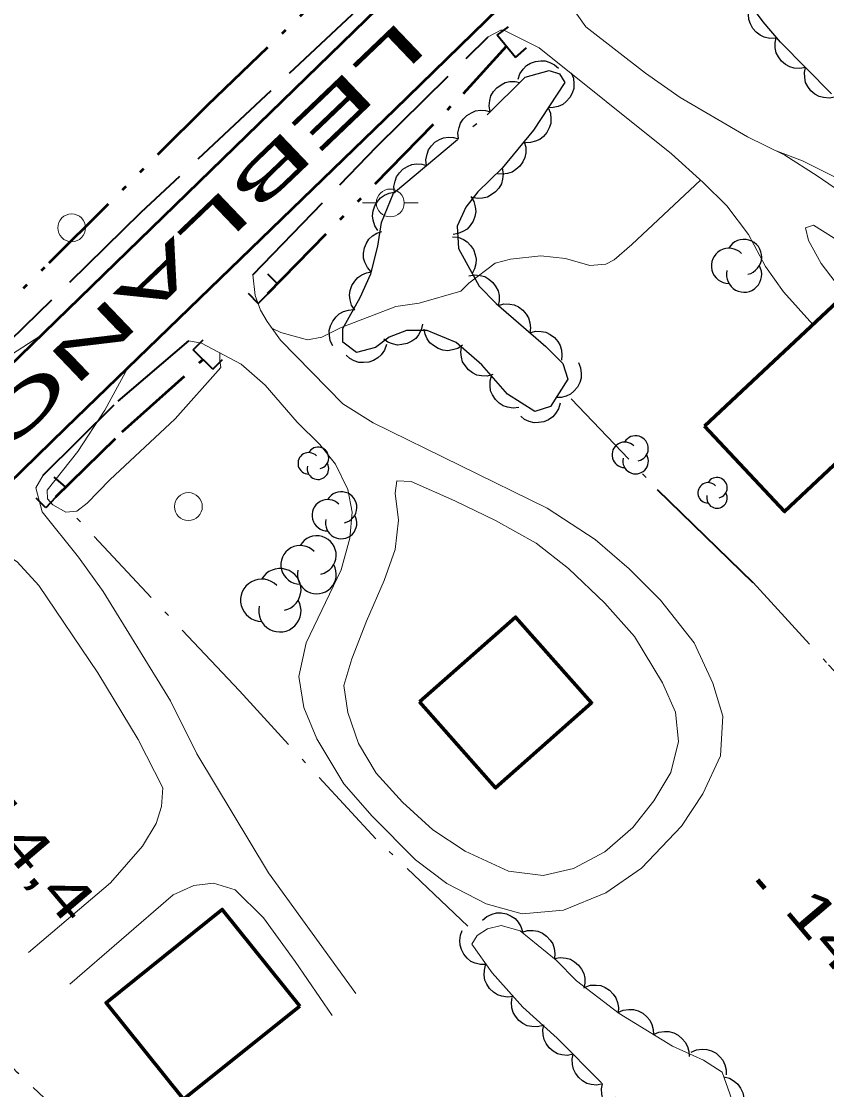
# Model space of a CAD drawing. Extents: x 386081 to 389416, y 5130568 to 5134082.
# Drawn here: x 387358.2 to 387416.1, y 5132218.5 to 5132295.3 of the extents above; entities that cross this region are included whole.
import ezdxf

# ---------------------------------------------------------------- set-up
doc = ezdxf.new("R2010")
doc.units = 0
doc.header["$LTSCALE"] = 1.2
for name, pattern in [('DASH_DOUBLE_DOT', [9.2, 5, -1.2, 0.3, -1.2, 0.3, -1.2]), ('DOT_DASHED', [7.7, 5, -1.2, 0.3, -1.2]), ('LONG_DASHED', [7.5, 6, -1.5])]:
    doc.linetypes.add(name, pattern=pattern)
for name, color, linetype, lineweight in [('19', 7, 'Continuous', 13), ('2', 7, 'Continuous', 13), ('21', 7, 'LONG_DASHED', 35), ('26', 7, 'Continuous', 35), ('3', 7, 'Continuous', 140), ('31', 7, 'Continuous', 70), ('36', 7, 'Continuous', 13), ('37', 7, 'Continuous', 13), ('4', 7, 'DASH_DOUBLE_DOT', 53), ('41', 7, 'DOT_DASHED', 25), ('44', 7, 'Continuous', 25)]:
    doc.layers.add(name, color=color, linetype=linetype, lineweight=lineweight)

msp = doc.modelspace()

# ---------------------------------------------------------------- linework, layer by layer
at = {"layer": '19'}
for points in [[(387422.4, 5132279.4), (387415.39, 5132284.23), (387413.06, 5132285.71), (387410.38, 5132287.04), (387405.54, 5132289.86), (387403.04, 5132291.62), (387398.75, 5132294.94), (387397.82, 5132296.26), (387397.26, 5132297.49), (387397.04, 5132298.28), (387397.11, 5132299.05)], [(387391.74, 5132294.23), (387392.64, 5132294.7), (387392.87, 5132294.71), (387395.39, 5132293.43), (387404.91, 5132285.8), (387407.18, 5132283.76), (387408.88, 5132282.08), (387410.44, 5132280.01), (387411.67, 5132277.71), (387412.95, 5132275.88), (387415.07, 5132273.55)], [(387417.37, 5132275.7), (387415.66, 5132277.92), (387414.75, 5132279.57), (387414.55, 5132280.48), (387415.11, 5132280.68), (387420.6, 5132277.22)], [(387370.22, 5132272.37), (387371.13, 5132272.19), (387373.99, 5132270.69), (387375.7, 5132269.18), (387378.01, 5132266.51), (387379.63, 5132264.92), (387380.77, 5132263.49), (387381.65, 5132261.67), (387381.95, 5132260.05), (387381.78, 5132258.18), (387381.18, 5132255.9), (387378.66, 5132250.65), (387378.13, 5132248.24), (387378.48, 5132246.01), (387379.41, 5132243.75), (387381.36, 5132240.51), (387383.4, 5132238.18), (387386.5, 5132235.04), (387388.76, 5132233.34), (387391.6, 5132231.88), (387394.18, 5132231.17), (387397.16, 5132231.44), (387400.2, 5132232.68), (387402.76, 5132234.45), (387405.63, 5132237.48), (387407.16, 5132239.79), (387408.44, 5132242.53), (387408.61, 5132245.37), (387407.88, 5132247.75), (387406.53, 5132250.65), (387404.11, 5132253.72), (387401.86, 5132255.97), (387399.42, 5132258.09), (387395.97, 5132260.34), (387383.46, 5132266.48), (387381.28, 5132267.83), (387376.8, 5132272.42), (387375.86, 5132273.76), (387375.38, 5132274.58), (387374.98, 5132275.62), (387374.83, 5132277.12)], [(387382.22, 5132225.44), (387375.94, 5132234.12), (387370.79, 5132242.67), (387368.9, 5132246.48), (387364.06, 5132254.34), (387362.3, 5132256.8), (387359.68, 5132260.08), (387359.22, 5132261.8), (387359.74, 5132262.7)], [(387354.62, 5132257.4), (387355.58, 5132257.49), (387356.56, 5132257.32), (387357.89, 5132256.48), (387359.45, 5132254.78), (387363.68, 5132248.49), (387366.57, 5132243.7), (387368.35, 5132240.22), (387368.26, 5132238.88), (387367.87, 5132237.67), (387366.88, 5132236.04), (387364.58, 5132233.4), (387358.69, 5132228.38)], [(387361.67, 5132226.11), (387369.09, 5132232.53), (387370.59, 5132233.2), (387371.99, 5132233.37), (387373.55, 5132232.9), (387375.59, 5132230.87), (387377.86, 5132227.74), (387380.53, 5132223.86)]]:
    msp.add_lwpolyline(points, dxfattribs=at)
msp.add_lwpolyline([(387386.2, 5132262.26), (387389.34, 5132260.86), (387392.26, 5132259.44), (387395.18, 5132257.83), (387397.5, 5132256), (387400.13, 5132253.51), (387402.26, 5132251.12), (387404.27, 5132247.78), (387405.2, 5132245.66), (387405.41, 5132243.57), (387404.87, 5132241.34), (387403.64, 5132239.3), (387402.13, 5132237.38), (387400.11, 5132235.63), (387397.87, 5132234.44), (387395.68, 5132233.93), (387393.2, 5132234.24), (387390.08, 5132235.67), (387387.75, 5132237.22), (387385.58, 5132239.2), (387383.69, 5132241.29), (387382.41, 5132243.41), (387381.65, 5132245.65), (387381.36, 5132247.59), (387381.94, 5132249.51), (387382.99, 5132252.2), (387384.25, 5132255.13), (387385.04, 5132257.36), (387385.28, 5132259.47), (387385.04, 5132261.42), (387385.18, 5132262.29)], close=True, dxfattribs=at)
at = {"layer": '2'}
for points in [[(387412.43, 5132286.03), (387414.32, 5132285.3), (387417.34, 5132283.8), (387424.57, 5132280.68), (387425.03, 5132281.2), (387427.59, 5132283.53), (387429.06, 5132284.43), (387430.72, 5132285.09), (387432.64, 5132285.42), (387435.02, 5132285.48), (387435.31, 5132285.52)], [(387376.19, 5132273.28), (387376.83, 5132272.97), (387378.76, 5132272.43), (387379.77, 5132272.63), (387381.17, 5132273.33), (387385.09, 5132274.84), (387386.77, 5132275.07), (387389.78, 5132275.94), (387390.34, 5132276.5), (387392.24, 5132277.95), (387393.35, 5132278.24), (387395.52, 5132278.48), (387397.3, 5132278.28), (387399.05, 5132277.78), (387400.2, 5132277.87), (387400.78, 5132278.18), (387402.07, 5132279.28), (387407, 5132283.92)], [(387292.79, 5132207.75), (387292.79, 5132208.61), (387293.85, 5132210.26), (387295.35, 5132212.1), (387296.15, 5132212.9), (387299.2, 5132216.39), (387299.95, 5132217.37), (387301.13, 5132219.15), (387304.17, 5132222.13), (387330.72, 5132247.76), (387336.49, 5132252.9), (387339.94, 5132256.42), (387350.61, 5132266.83), (387352.3, 5132268.05), (387359.5, 5132272.69)], [(387365.84, 5132270.42), (387364.19, 5132267.38), (387362.24, 5132264.41), (387360.03, 5132261.63), (387360.06, 5132261), (387360.45, 5132260.57), (387361.39, 5132260.04), (387362.18, 5132260.13), (387362.91, 5132260.69), (387364.54, 5132262.36), (387369.23, 5132266.75), (387372.52, 5132270.44), (387372.44, 5132270.96), (387372.46, 5132271.49)]]:
    msp.add_lwpolyline(points, dxfattribs=at)
at = {"layer": '21'}
for points in [[(387559.78, 5132467.9), (387547.05, 5132455.63), (387529.68, 5132439.13), (387509.18, 5132419.17), (387475.58, 5132387.34), (387460.99, 5132373.08), (387444.91, 5132357.61), (387431.84, 5132344.48), (387417.82, 5132331.23), (387408.06, 5132321.28), (387397.84, 5132311.09), (387382.67, 5132296.51), (387366.78, 5132281.59), (387351.61, 5132266.75), (387342.14, 5132257.75), (387333.42, 5132249.15), (387330.68, 5132246.34), (387329.25, 5132245.05), (387325.03, 5132240.88), (387315.96, 5132231.51), (387312.59, 5132228.76), (387303.02, 5132219.72), (387274.55, 5132192.18)], [(387374.83, 5132277.12), (387383.74, 5132286.34), (387391.74, 5132294.23)], [(387359.74, 5132262.7), (387365.13, 5132268.03), (387370.22, 5132272.37)]]:
    msp.add_lwpolyline(points, dxfattribs=at)
at = {"layer": '21', "linetype": 'Continuous', "lineweight": 53}
for points in [[(387012.51, 5131910.8), (387021.08, 5131926.01), (387027.11, 5131935.62), (387032.84, 5131944.26), (387041.79, 5131956.43), (387052.62, 5131969.96), (387063.03, 5131981.26), (387078.48, 5131997.51), (387098.33, 5132017.4), (387121.9, 5132040.2), (387177.29, 5132094.24), (387231.65, 5132148.34), (387255.86, 5132172.16), (387275.84, 5132191.54), (387323.76, 5132237.29), (387346.1, 5132259.65), (387398.36, 5132310.48), (387454.62, 5132364.63)], [(387190.72, 5132099), (387248.29, 5132155.99), (387268.9, 5132176.09), (387312.71, 5132218.45), (387334.53, 5132239.9), (387361.38, 5132266.11), (387385.04, 5132289.01), (387424.23, 5132327.22)]]:
    msp.add_lwpolyline(points, dxfattribs=at)
at = {"layer": '26'}
for p, q in [((387392.39, 5132294.33), (387393.19, 5132294.93)), ((387393.69, 5132292.73), (387392.39, 5132294.33)), ((387393.69, 5132292.73), (387394.49, 5132293.43)), ((387376.6, 5132276.46), (387375.9, 5132277.16)), ((387376.6, 5132276.46), (387375.9, 5132277.16)), ((387375.2, 5132275.06), (387374.5, 5132275.76)), ((387375.2, 5132275.06), (387374.5, 5132275.76)), ((387376.6, 5132276.46), (387375.2, 5132275.06)), ((387376.6, 5132276.46), (387375.2, 5132275.06)), ((387370.54, 5132271.73), (387371.24, 5132272.43)), ((387370.54, 5132271.73), (387371.24, 5132272.43)), ((387371.94, 5132270.33), (387370.54, 5132271.73)), ((387371.94, 5132270.33), (387370.54, 5132271.73)), ((387371.94, 5132270.33), (387372.64, 5132271.03)), ((387371.94, 5132270.33), (387372.64, 5132271.03)), ((387361.35, 5132261.86), (387360.55, 5132262.56)), ((387361.35, 5132261.86), (387360.55, 5132262.56)), ((387361.35, 5132261.86), (387359.95, 5132260.36)), ((387361.35, 5132261.86), (387359.95, 5132260.36)), ((387359.95, 5132260.36), (387359.25, 5132261.06)), ((387359.95, 5132260.36), (387359.25, 5132261.06))]:
    msp.add_line(p, q, dxfattribs=at)
at = {"layer": '3'}
msp.add_line((387411.1, 5132233.62), (387411.61, 5132233.01), dxfattribs=at)
at = {"layer": '31'}
for points in [[(387407.29, 5132266.22), (387418.37, 5132276.62), (387424.55, 5132270.04), (387419.78, 5132265.55), (387419.34, 5132266.01), (387413.04, 5132260.09)], [(387386.8, 5132246.4), (387393.7, 5132252.51), (387399.17, 5132246.34), (387392.27, 5132240.22)], [(387378.19, 5132224.54), (387369.84, 5132217.84), (387364.27, 5132224.78), (387372.62, 5132231.49)]]:
    msp.add_lwpolyline(points, close=True, dxfattribs=at)
at = {"layer": '36'}
for p, q in [((387382.7, 5132282.28), (387383.7, 5132282.28)), ((387386.7, 5132282.28), (387385.7, 5132282.28))]:
    msp.add_line(p, q, dxfattribs=at)
for centre in [(387384.694, 5132282.28), (387361.798, 5132280.49), (387370.188, 5132260.45)]:
    msp.add_circle(centre, 1, dxfattribs=at)
at = {"layer": '37', "lineweight": 25}
for p, q in [((387403.88, 5132261.65), (387410.76, 5132254.97)), ((387403.91, 5132261.68), (387410.79, 5132255))]:
    msp.add_line(p, q, dxfattribs=at)
at = {"layer": '4'}
for points in [[(387309.12, 5132228.67), (387320.14, 5132238.92), (387332.54, 5132251.32), (387345.1, 5132263.26), (387360.19, 5132277.97), (387371.56, 5132289.32), (387382.38, 5132299.68), (387391.28, 5132308.57), (387395.06, 5132312.61), (387395.98, 5132313.9), (387396.57, 5132318.63), (387396.55, 5132322.58), (387396.22, 5132327.79)], [(387375.9, 5132275.76), (387389.95, 5132290.15), (387393.05, 5132293.54)], [(387360.65, 5132261.16), (387365.44, 5132265.82), (387371.24, 5132271.03)]]:
    msp.add_lwpolyline(points, dxfattribs=at)
at = {"layer": '41'}
msp.add_line((387397.71, 5132268.2), (387403.91, 5132261.68), dxfattribs=at)
for points in [[(387390.27, 5132230.29), (387383.66, 5132236.56), (387373.85, 5132247.19), (387362.06, 5132259.73)], [(387410.79, 5132255), (387416.19, 5132249.07), (387424.53, 5132240.16)], [(387363.42, 5132214.58), (387357.88, 5132219.77), (387345.26, 5132233.24), (387341.64, 5132237.16)]]:
    msp.add_lwpolyline(points, dxfattribs=at)
at = {"layer": '44', "linetype": 'DOT_DASHED'}
msp.add_lwpolyline([(387416.42, 5132290.12), (387412.74, 5132293.83), (387411.51, 5132295.31), (387410.04, 5132297.29), (387409.56, 5132298.77), (387410.06, 5132299.75), (387410.81, 5132300.24), (387412.29, 5132299.74), (387415.61, 5132297.14), (387419.79, 5132294.42)], dxfattribs=at)
at = {"layer": '44'}
for points in [[(387412.39, 5132294.12), (387411.98, 5132294.1), (387411.58, 5132294.2), (387411.28, 5132294.33), (387411, 5132294.55), (387410.76, 5132294.82), (387410.58, 5132295.16), (387410.47, 5132295.47), (387410.45, 5132295.82), (387410.49, 5132296.19), (387410.61, 5132296.53)], [(387414.54, 5132292.01), (387414.13, 5132291.94), (387413.73, 5132291.98), (387413.41, 5132292.06), (387413.1, 5132292.24), (387412.82, 5132292.48), (387412.6, 5132292.79), (387412.44, 5132293.07), (387412.37, 5132293.42), (387412.36, 5132293.79), (387412.43, 5132294.14)], [(387393.88, 5132291.18), (387394.02, 5132291.57), (387394.25, 5132291.9), (387394.48, 5132292.15), (387394.78, 5132292.32), (387395.13, 5132292.45), (387395.51, 5132292.49), (387395.84, 5132292.49), (387396.17, 5132292.38), (387396.5, 5132292.21), (387396.78, 5132291.98)], [(387416.65, 5132289.88), (387416.24, 5132289.81), (387415.84, 5132289.85), (387415.52, 5132289.93), (387415.22, 5132290.11), (387414.93, 5132290.35), (387414.71, 5132290.66), (387414.55, 5132290.94), (387414.49, 5132291.29), (387414.47, 5132291.66), (387414.54, 5132292.01)], [(387397.69, 5132291.63), (387397.86, 5132291.25), (387397.9, 5132290.84), (387397.89, 5132290.51), (387397.78, 5132290.18), (387397.6, 5132289.86), (387397.34, 5132289.57), (387397.1, 5132289.36), (387396.77, 5132289.22), (387396.41, 5132289.13), (387396.05, 5132289.12)], [(387391.88, 5132288.84), (387391.81, 5132289.25), (387391.85, 5132289.65), (387391.93, 5132289.97), (387392.11, 5132290.28), (387392.35, 5132290.56), (387392.66, 5132290.78), (387392.95, 5132290.94), (387393.3, 5132291), (387393.67, 5132291.02), (387394.02, 5132290.94)], [(387389.6, 5132286.89), (387389.56, 5132287.31), (387389.64, 5132287.71), (387389.74, 5132288.02), (387389.94, 5132288.31), (387390.2, 5132288.57), (387390.54, 5132288.76), (387390.83, 5132288.9), (387391.18, 5132288.94), (387391.55, 5132288.92), (387391.9, 5132288.82)], [(387396.05, 5132289.12), (387396.21, 5132288.74), (387396.25, 5132288.33), (387396.24, 5132288), (387396.13, 5132287.67), (387395.96, 5132287.34), (387395.7, 5132287.06), (387395.45, 5132286.85), (387395.13, 5132286.71), (387394.77, 5132286.62), (387394.41, 5132286.61)], [(387387.3, 5132284.96), (387387.26, 5132285.38), (387387.34, 5132285.78), (387387.44, 5132286.09), (387387.65, 5132286.38), (387387.91, 5132286.64), (387388.24, 5132286.83), (387388.53, 5132286.97), (387388.88, 5132287.01), (387389.25, 5132286.99), (387389.6, 5132286.89)], [(387394.31, 5132286.68), (387394.43, 5132286.28), (387394.43, 5132285.88), (387394.38, 5132285.55), (387394.23, 5132285.23), (387394.02, 5132284.93), (387393.73, 5132284.68), (387393.46, 5132284.49), (387393.12, 5132284.39), (387392.76, 5132284.34), (387392.4, 5132284.38)], [(387385.01, 5132283.03), (387384.96, 5132283.45), (387385.04, 5132283.85), (387385.15, 5132284.16), (387385.35, 5132284.45), (387385.61, 5132284.71), (387385.94, 5132284.91), (387386.24, 5132285.04), (387386.59, 5132285.08), (387386.96, 5132285.06), (387387.3, 5132284.96)], [(387392.74, 5132284.79), (387392.82, 5132284.38), (387392.77, 5132283.98), (387392.69, 5132283.65), (387392.51, 5132283.35), (387392.27, 5132283.07), (387391.96, 5132282.85), (387391.68, 5132282.69), (387391.33, 5132282.62), (387390.96, 5132282.61), (387390.61, 5132282.68)], [(387383.81, 5132280.29), (387383.58, 5132280.64), (387383.47, 5132281.03), (387383.42, 5132281.36), (387383.47, 5132281.71), (387383.58, 5132282.06), (387383.79, 5132282.38), (387383.99, 5132282.64), (387384.28, 5132282.83), (387384.62, 5132282.99), (387384.97, 5132283.06)], [(387390.49, 5132282.74), (387390.7, 5132282.38), (387390.8, 5132281.99), (387390.84, 5132281.66), (387390.78, 5132281.31), (387390.65, 5132280.97), (387390.43, 5132280.65), (387390.22, 5132280.4), (387389.92, 5132280.22), (387389.58, 5132280.08), (387389.22, 5132280.02)], [(387383.32, 5132277.32), (387383.05, 5132277.64), (387382.88, 5132278.01), (387382.78, 5132278.32), (387382.78, 5132278.67), (387382.84, 5132279.04), (387383, 5132279.39), (387383.16, 5132279.67), (387383.42, 5132279.91), (387383.74, 5132280.11), (387384.08, 5132280.23)], [(387389.16, 5132279.85), (387389.57, 5132279.81), (387389.95, 5132279.65), (387390.23, 5132279.49), (387390.47, 5132279.23), (387390.68, 5132278.92), (387390.8, 5132278.56), (387390.87, 5132278.24), (387390.84, 5132277.89), (387390.75, 5132277.53), (387390.59, 5132277.21)], [(387382.15, 5132274.57), (387381.92, 5132274.92), (387381.81, 5132275.31), (387381.77, 5132275.64), (387381.82, 5132275.98), (387381.94, 5132276.34), (387382.15, 5132276.66), (387382.36, 5132276.91), (387382.65, 5132277.1), (387382.99, 5132277.25), (387383.34, 5132277.32)], [(387390.35, 5132277.04), (387390.76, 5132277.11), (387391.17, 5132277.07), (387391.49, 5132276.99), (387391.79, 5132276.81), (387392.07, 5132276.57), (387392.29, 5132276.25), (387392.45, 5132275.97), (387392.52, 5132275.62), (387392.53, 5132275.25), (387392.46, 5132274.9)], [(387392.47, 5132274.91), (387392.87, 5132275.02), (387393.28, 5132275.01), (387393.61, 5132274.95), (387393.92, 5132274.8), (387394.22, 5132274.58), (387394.46, 5132274.28), (387394.64, 5132274.01), (387394.74, 5132273.67), (387394.78, 5132273.3), (387394.73, 5132272.95)], [(387380.58, 5132272), (387380.39, 5132272.37), (387380.32, 5132272.77), (387380.31, 5132273.1), (387380.4, 5132273.45), (387380.56, 5132273.78), (387380.8, 5132274.08), (387381.03, 5132274.31), (387381.34, 5132274.47), (387381.7, 5132274.58), (387382.05, 5132274.61)], [(387387.02, 5132273.56), (387386.93, 5132273.15), (387386.73, 5132272.8), (387386.53, 5132272.54), (387386.24, 5132272.33), (387385.91, 5132272.17), (387385.54, 5132272.09), (387385.21, 5132272.06), (387384.87, 5132272.14), (387384.52, 5132272.27), (387384.23, 5132272.48)], [(387389.9, 5132272.05), (387389.55, 5132271.82), (387389.16, 5132271.71), (387388.83, 5132271.65), (387388.48, 5132271.7), (387388.13, 5132271.81), (387387.81, 5132272.02), (387387.55, 5132272.22), (387387.35, 5132272.51), (387387.2, 5132272.85), (387387.13, 5132273.2)], [(387394.73, 5132272.95), (387395.14, 5132273.05), (387395.54, 5132273.04), (387395.87, 5132272.98), (387396.19, 5132272.83), (387396.49, 5132272.61), (387396.73, 5132272.32), (387396.91, 5132272.04), (387397, 5132271.7), (387397.04, 5132271.34), (387397, 5132270.98)], [(387384.42, 5132272.1), (387384.28, 5132271.7), (387384.04, 5132271.37), (387383.81, 5132271.14), (387383.5, 5132270.96), (387383.15, 5132270.84), (387382.77, 5132270.8), (387382.45, 5132270.81), (387382.11, 5132270.92), (387381.79, 5132271.1), (387381.52, 5132271.33)], [(387392.07, 5132269.94), (387391.67, 5132269.83), (387391.26, 5132269.85), (387390.93, 5132269.9), (387390.62, 5132270.06), (387390.32, 5132270.28), (387390.08, 5132270.58), (387389.9, 5132270.85), (387389.81, 5132271.19), (387389.77, 5132271.56), (387389.81, 5132271.91)], [(387398.22, 5132270.81), (387398.38, 5132270.43), (387398.43, 5132270.02), (387398.42, 5132269.69), (387398.32, 5132269.36), (387398.15, 5132269.03), (387397.89, 5132268.75), (387397.65, 5132268.53), (387397.33, 5132268.38), (387396.97, 5132268.29), (387396.61, 5132268.28)], [(387393.94, 5132267.58), (387393.53, 5132267.53), (387393.13, 5132267.6), (387392.81, 5132267.7), (387392.52, 5132267.89), (387392.25, 5132268.15), (387392.05, 5132268.48), (387391.91, 5132268.77), (387391.87, 5132269.12), (387391.88, 5132269.49), (387391.97, 5132269.84)], [(387396.92, 5132267.88), (387396.8, 5132267.48), (387396.58, 5132267.14), (387396.37, 5132266.89), (387396.07, 5132266.69), (387395.73, 5132266.55), (387395.36, 5132266.49), (387395.03, 5132266.48), (387394.69, 5132266.57), (387394.35, 5132266.72), (387394.07, 5132266.94)], [(387391.32, 5132230.71), (387391.63, 5132230.98), (387392.01, 5132231.14), (387392.33, 5132231.23), (387392.68, 5132231.23), (387393.04, 5132231.16), (387393.39, 5132231), (387393.67, 5132230.83), (387393.9, 5132230.56), (387394.09, 5132230.25), (387394.21, 5132229.9)], [(387391.61, 5132227.53), (387391.19, 5132227.52), (387390.8, 5132227.62), (387390.49, 5132227.75), (387390.22, 5132227.98), (387389.98, 5132228.26), (387389.82, 5132228.6), (387389.71, 5132228.91), (387389.69, 5132229.26), (387389.74, 5132229.63), (387389.87, 5132229.97)], [(387394.17, 5132229.84), (387394.57, 5132229.96), (387394.98, 5132229.96), (387395.31, 5132229.92), (387395.63, 5132229.77), (387395.93, 5132229.56), (387396.19, 5132229.28), (387396.37, 5132229.01), (387396.48, 5132228.67), (387396.53, 5132228.31), (387396.5, 5132227.95)], [(387393.54, 5132225.23), (387393.12, 5132225.18), (387392.72, 5132225.24), (387392.4, 5132225.34), (387392.11, 5132225.54), (387391.84, 5132225.79), (387391.64, 5132226.12), (387391.5, 5132226.41), (387391.45, 5132226.76), (387391.46, 5132227.13), (387391.55, 5132227.48)], [(387396.51, 5132227.96), (387396.92, 5132228.04), (387397.33, 5132227.99), (387397.65, 5132227.91), (387397.95, 5132227.73), (387398.23, 5132227.49), (387398.45, 5132227.18), (387398.61, 5132226.89), (387398.68, 5132226.55), (387398.69, 5132226.18), (387398.62, 5132225.82)], [(387398.69, 5132225.9), (387399.08, 5132226.04), (387399.49, 5132226.05), (387399.82, 5132226.01), (387400.14, 5132225.88), (387400.45, 5132225.68), (387400.72, 5132225.4), (387400.91, 5132225.14), (387401.03, 5132224.8), (387401.09, 5132224.44), (387401.07, 5132224.08)], [(387395.68, 5132223.14), (387395.28, 5132223.04), (387394.87, 5132223.06), (387394.54, 5132223.12), (387394.23, 5132223.28), (387393.94, 5132223.51), (387393.7, 5132223.81), (387393.53, 5132224.08), (387393.44, 5132224.42), (387393.4, 5132224.79), (387393.45, 5132225.15)], [(387401.06, 5132224.07), (387401.44, 5132224.24), (387401.85, 5132224.29), (387402.18, 5132224.29), (387402.51, 5132224.19), (387402.84, 5132224.02), (387403.13, 5132223.77), (387403.35, 5132223.53), (387403.5, 5132223.21), (387403.6, 5132222.85), (387403.61, 5132222.49)], [(387397.85, 5132221.07), (387397.43, 5132220.99), (387397.03, 5132221.03), (387396.71, 5132221.11), (387396.41, 5132221.29), (387396.12, 5132221.53), (387395.9, 5132221.84), (387395.75, 5132222.13), (387395.68, 5132222.47), (387395.66, 5132222.84), (387395.73, 5132223.2)], [(387403.61, 5132222.49), (387404, 5132222.66), (387404.4, 5132222.72), (387404.73, 5132222.71), (387405.07, 5132222.61), (387405.4, 5132222.45), (387405.68, 5132222.19), (387405.9, 5132221.95), (387406.05, 5132221.63), (387406.15, 5132221.28), (387406.17, 5132220.92)], [(387406.33, 5132221.22), (387406.71, 5132221.38), (387407.12, 5132221.43), (387407.45, 5132221.42), (387407.78, 5132221.31), (387408.11, 5132221.14), (387408.39, 5132220.88), (387408.61, 5132220.64), (387408.75, 5132220.31), (387408.84, 5132219.96), (387408.85, 5132219.6)], [(387399.96, 5132218.94), (387399.55, 5132218.86), (387399.14, 5132218.9), (387398.82, 5132218.98), (387398.52, 5132219.16), (387398.24, 5132219.4), (387398.02, 5132219.71), (387397.86, 5132220), (387397.79, 5132220.34), (387397.78, 5132220.71), (387397.85, 5132221.07)], [(387402.07, 5132216.81), (387401.66, 5132216.73), (387401.26, 5132216.77), (387400.93, 5132216.85), (387400.63, 5132217.03), (387400.35, 5132217.27), (387400.13, 5132217.58), (387399.97, 5132217.87), (387399.9, 5132218.21), (387399.89, 5132218.58), (387399.96, 5132218.94)], [(387408.67, 5132219.45), (387409.07, 5132219.35), (387409.42, 5132219.14), (387409.68, 5132218.93), (387409.88, 5132218.64), (387410.03, 5132218.3), (387410.1, 5132217.93), (387410.12, 5132217.6), (387410.04, 5132217.26), (387409.89, 5132216.92), (387409.68, 5132216.63)]]:
    msp.add_lwpolyline(points, dxfattribs=at)
at = {"layer": '44', "linetype": 'DOT_DASHED'}
msp.add_lwpolyline([(387392.74, 5132284.79), (387391, 5132283.07), (387390.13, 5132281.97), (387389.5, 5132280.62), (387389.61, 5132279.01), (387391.08, 5132276.3), (387392.3, 5132275.06), (387395.87, 5132271.96), (387397.1, 5132270.73), (387397.46, 5132269.62), (387396.21, 5132267.65), (387395.09, 5132267.28), (387393.12, 5132268.52), (387391.28, 5132270.63), (387389.44, 5132272.24), (387387.34, 5132273.11), (387385.86, 5132273.11), (387384.62, 5132272.63), (387383.63, 5132271.89), (387382.26, 5132271.53), (387381.28, 5132272.27), (387381.29, 5132273.26), (387382.54, 5132275.47), (387383.29, 5132277.19), (387383.8, 5132279.16), (387384.06, 5132280.88), (387384.94, 5132282.98), (387391.66, 5132288.62), (387394.4, 5132291.32), (387396.13, 5132291.8), (387396.87, 5132291.56), (387397.24, 5132290.94), (387394.99, 5132287.5)], close=True, dxfattribs=at)
at = {"layer": '44', "linetype": 'DOT_DASHED', "lineweight": 13}
msp.add_lwpolyline([(387406.39, 5132212.45), (387396.69, 5132222.23), (387394.23, 5132224.45), (387392.03, 5132226.93), (387390.57, 5132228.98), (387390.95, 5132229.6), (387391.69, 5132230.08), (387392.68, 5132230.33), (387394.04, 5132229.95), (387396.62, 5132227.85), (387398.09, 5132226.36), (387401.16, 5132224.01), (387404.98, 5132221.65), (387407.2, 5132220.66), (387408.55, 5132219.79), (387409.52, 5132217.07)], dxfattribs=at)
at = {"layer": '44'}
for centre, radius, start, end in [((387410.129, 5132278.392), 1.266, 282.26917, 149.72626), ((387409.04, 5132277.759), 1.266, 44.11537, 269.80396), ((387410.129, 5132277.126), 1.266, 166.93686, 29.62122), ((387401.546, 5132264.171), 0.914, 44.11537, 269.80396), ((387402.332, 5132264.628), 0.914, 282.26917, 149.72626), ((387378.838, 5132263.558), 0.773, 44.11537, 269.80396), ((387379.503, 5132263.944), 0.773, 282.26917, 149.72626), ((387379.503, 5132263.171), 0.773, 166.93686, 29.62122), ((387402.332, 5132263.714), 0.914, 166.93686, 29.62122), ((387407.544, 5132261.437), 0.737, 44.11537, 269.80396), ((387408.178, 5132261.805), 0.737, 282.26917, 149.72626), ((387381.171, 5132260.389), 1.127, 282.26917, 149.72626), ((387408.178, 5132261.068), 0.737, 166.93686, 29.62122), ((387380.201, 5132259.826), 1.127, 44.11537, 269.80396), ((387381.171, 5132259.262), 1.127, 166.93686, 29.62122), ((387379.421, 5132256.957), 1.391, 282.26917, 149.72626), ((387378.225, 5132256.262), 1.391, 44.11537, 269.80396), ((387376.765, 5132254.475), 1.52, 282.26917, 149.72626), ((387379.421, 5132255.566), 1.391, 166.93686, 29.62122), ((387375.458, 5132253.715), 1.52, 44.11537, 269.80396), ((387376.765, 5132252.954), 1.52, 166.93686, 29.62122)]:
    msp.add_arc(centre, radius, start, end, dxfattribs=at)

# ---------------------------------------------------------------- texts
at = {"layer": '21', "width": 2.3}
msp.add_text('LEBLANC', height=3, rotation=223.71, dxfattribs=at).set_placement((387385.48, 5132295.57))
at = {"layer": '3', "width": 1.4}
for s, p in [('14,4   ', (387354.38, 5132238.62)), ('14,5   ', (387412.93, 5132231.4))]:
    msp.add_text(s, height=3, rotation=310.294, dxfattribs=at).set_placement(p)

doc.saveas('drawing.dxf')
